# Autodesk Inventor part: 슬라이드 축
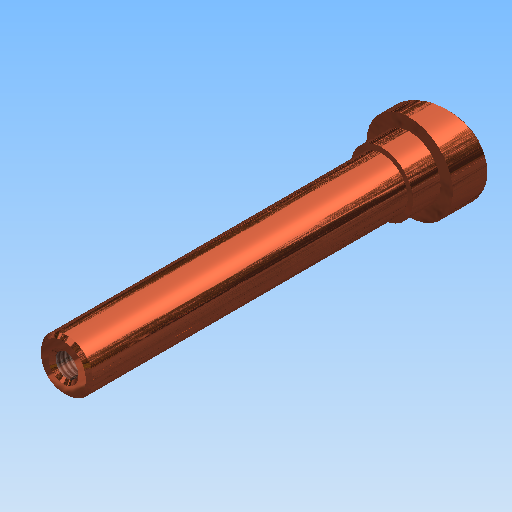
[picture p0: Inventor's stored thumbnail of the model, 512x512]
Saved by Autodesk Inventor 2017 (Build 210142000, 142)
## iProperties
Created: 2021-07
Part Number: 슬라이드 축
Document SubType Name: 모델링
Designer: mdu
Mass: 21.572 g
Surface Area: 67.5858 cm^2
Volume: 21.572 cm^3
Density: 1 g/cm^3
Material: 일반
Appearance: 금속 1400F 열
변환 표준: STEP AP214IS
파일 이름: C:\Users\SeoGD\Desktop\?쒗뿕\異?stp
전처리기: Build: 253, Release: 2010 SP1 - Date: Wed 07/29/2009
전송 단위: 밀리미터
불확실성: 0.01
Author: mdu
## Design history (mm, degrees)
sketch "스케치1"
  geometry: L1 (0, 100)-(7.5, 100); L2 (7.5, 100)-(7.5, 0); L3 (7.5, 0)-(12.5, 0); L4 (12.5, 0)-(12.5, -17); L5 (12.5, -17)-(0, -17); L6 (0, -17)-(0, 100); 1 further point
  constraints: 12 end point, 2 parallel, 2 point on line, 1 perpendicular, 1 vertical
  dimensions: "d0" = 100 distance from line of L1 point (0, 0); "d1" = 15 diameter of L2 L6; "d2" = 25 diameter of L4 L6; "d3" = 17 distance of L3.end L4.end
revolve "회전1" sketch "스케치1" stored, may be unused: angle "d4" = 90 deg
sketch "스케치2"
  geometry: L1 (12.5, 0)-(12.5, -17) reference; L2 (-12.5, -17)-(12.5, -17) reference; L3 (-12.5, 0)-(-12.5, -17) reference; L4 (12.5, -5)-(-12.5, -11.699); L5 (-12.5, 0)-(12.5, 0) reference; 1 further point
  constraints: 2 end point, 2 point on line
  dimensions: "d5" = 75 deg angle of L1 L4; "d6" = 5 distance from line of L4.start L5
extrude "돌출1" cut sketch "스케치2" stored distance "d7" = 10; taper "d8" = 0 deg
chamfer "모따기1" distance "d9" = 1; stored, may be unused: second distance "d10" = 2, angle "d11" = 45 deg
fillet "모깎기1" dims "d12" = 0.5
hole "구멍1" diameter "d15" = 6.647; stored, may be unused: countersink angle "d19" = 90 deg, drill point angle "d21" = 118 deg; dims "d13" = 10, "d14" = 10, "d16" = 17, "d17" = 4, "d18" = 2, "d20" = 20
chamfer "모따기2" distance "d22" = 1; stored, may be unused: second distance "d23" = 2, angle "d24" = 45 deg
sketch "스케치3"
  geometry: C1 r 9 at (0, 0); 1 further point
  constraints: 1 centre point, 1 coincident
  dimensions: "d25" = 18 diameter of C1
extrude "돌출2" join sketch "스케치3" distance "d26" = 8; taper "d27" = 0 deg
node "솔리드1"
node "솔리드 본체"
node "곡면 본체"
node "솔리드2"
